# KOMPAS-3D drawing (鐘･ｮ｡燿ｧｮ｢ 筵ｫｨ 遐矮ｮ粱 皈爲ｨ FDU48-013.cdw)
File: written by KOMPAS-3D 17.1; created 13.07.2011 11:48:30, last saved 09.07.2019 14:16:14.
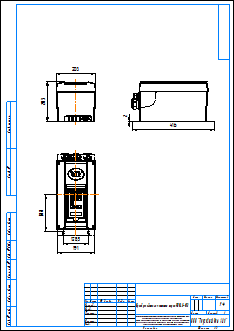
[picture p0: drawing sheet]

Title block, sheet 1: name: Преобразователи частоты серии FDU48-013; scale: 1:4; sheets: 1; sheet format: A3; stored path: \\adlc.lan\data\АДЛ_ПКД\3D-модели\Поставщики\Оборудование Emotron\Преобразователи частоты\Серия FDU 2.0\KOMPAS 2D\Преобразователи частоты серии FDU48-013.cdw

Views: Спереди 1
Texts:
  Рама для чертежей
  Лит-Масса-Масштаб
  Материал-Предприятие
  Масштаб
  Изм.
  Лист
  № докум.
  Подп.
  Дата
  Лит.
  Разраб.
  Пров.
  Т.контр.
  Листов
  Внимание! Данный продукт является объектом авторского права ООО «Торговый Дом АДЛ».
  Запрещается изменение, копирование, распространение
  (в том числе путем копирования на другие сайты и ресурсы в Интернете)
  или любое иное использование информации и объектов без предварительного
  согласия правообладателя (ООО «Торговый Дом АДЛ»).
  Н.контр.
  Утв.
  ООО "Торговый дом АДЛ"
  Изменение
  Номер документа
  Подпись
  Обозначение документа
  Наименование изделия
  Масса изделия по ГОСТ 2.109-73
  Порядковый номер листа
  Общее количество листов в документе
  Характер работы, выполненной лицом, подписавшим документ
  Наименование или индекс предприятия, выпускающего документ
  Инв. № подл.
  Подп. и дата
  Взам. инв. №
  Инв. № дубл.
  Инвентарный номер подлинника по ГОСТ 2.501-68
  Подпись принявшего подлинник в отдел технической документации
  Инвентарный номер подлинника, взамен которого выпущен данный подлинник
  Инвентарный номер дубликата по ГОСТ 2.502-68
  Подпись принявшего дубликат в отдел технической документации
  Справ. №
  Перв. примен.
  Обозначение документа, взамен или на основании которого выпущен данный документ
  Обозначение документа, в котором впервые записан данный документ
  Подпись лица, копировавшего чертеж
  Обозначение формата листа
  !Рама для чертежа
Dimensions and other numbers on the sheet: 203; 128,5; 191; 416; 2; 188; 1:4; 1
